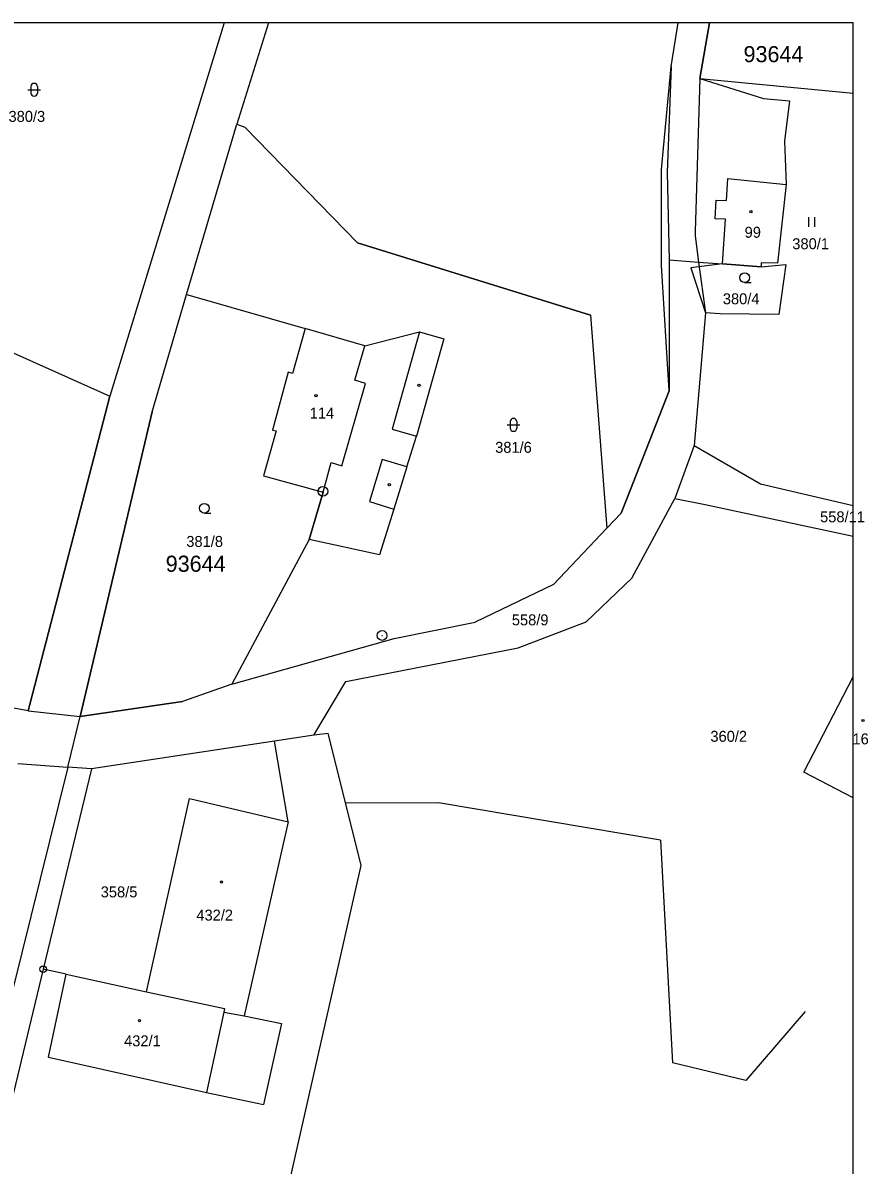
# Model space of a CAD drawing. Extents: x -778045 to -768365, y -1202571 to -1202059.
# Drawn here: x -777753.6 to -777622.5, y -1202457.4 to -1202280.1 of the extents above; entities that cross this region are included whole.
import ezdxf

# ---------------------------------------------------------------- set-up
doc = ezdxf.new("R2010")
doc.units = 0
for name, color, linetype in [('BPEJ', 7, 'Continuous'), ('Katastr_Hranice parcel', 7, 'Continuous'), ('Katastr_Parcelní čísla', 7, 'Continuous'), ('Katastr_Slučkované čáry', 7, 'Continuous'), ('Katastr_Značky kultur', 7, 'Continuous')]:
    doc.layers.add(name, color=color, linetype=linetype)

msp = doc.modelspace()

# ---------------------------------------------------------------- linework, layer by layer
at = {"layer": 'BPEJ'}
for points in [[(-777715.51, -1202280.12), (-777720.45, -1202295.86), (-777719.2, -1202296.33), (-777701.71, -1202314.27), (-777665.58, -1202325.46), (-777663.01, -1202358.54), (-777660.78, -1202356.18), (-777659.91, -1202353.96), (-777653.34, -1202337.23), (-777654.57, -1202317.8), (-777654.55, -1202302.89), (-777653.05, -1202286.88), (-777651.96, -1202280.12)], [(-777647.08, -1202280.12), (-777648.6, -1202288.78), (-777638.72, -1202291.84), (-777634.69, -1202292.2), (-777635.48, -1202298.47), (-777635.2, -1202305.22), (-777636.54, -1202317.41), (-777639.06, -1202317.35), (-777639.1, -1202318), (-777645.06, -1202317.53), (-777650.01, -1202318.12), (-777647.71, -1202325.12), (-777649.49, -1202345.7), (-777639.21, -1202351.67), (-777624.79, -1202354.99)], [(-777788.3, -1202316.49), (-777774.01, -1202322.88), (-777740.14, -1202338.03), (-777752.8, -1202386.89), (-777773.14, -1202383.15), (-777779.27, -1202388.61), (-777811.7, -1202375.6), (-777805.7, -1202356.3), (-777793.87, -1202330.63), (-777788.3, -1202316.49)], [(-777728.24, -1202322.3), (-777726.98, -1202322.66), (-777709.85, -1202327.57), (-777711.82, -1202334.53), (-777712.49, -1202334.34), (-777714.9, -1202343.3), (-777714.35, -1202343.45), (-777716.32, -1202350.41), (-777707.07, -1202352.95), (-777709.23, -1202360.29), (-777721.22, -1202382.72), (-777728.85, -1202385.43), (-777744.73, -1202387.77), (-777733.6, -1202340.49), (-777728.24, -1202322.3)]]:
    msp.add_lwpolyline(points, dxfattribs=at)
at = {"layer": 'Defpoints'}
for p, q in [((-777624.79, -1202280.12), (-778044.79, -1202280.12)), ((-777624.79, -1202569.12), (-777624.79, -1202280.12))]:
    msp.add_line(p, q, dxfattribs=at)
at = {"layer": 'Katastr_Hranice parcel'}
for p, q in [((-777648.6, -1202288.78), (-777624.79, -1202291.01)), ((-777714.61, -1202391.58), (-777743, -1202395.86)), ((-777708.49, -1202390.66), (-777714.61, -1202391.58)), ((-777712.49, -1202404.11), (-777714.61, -1202391.58)), ((-777743, -1202395.86), (-777750.49, -1202426.97)), ((-777750.49, -1202426.97), (-777772.39, -1202517.89)), ((-777746.91, -1202427.75), (-777750.49, -1202426.97))]:
    msp.add_line(p, q, dxfattribs=at)
for points in [[(-777722.39, -1202280.12), (-777740.14, -1202338.03)], [(-777715.51, -1202280.12), (-777720.45, -1202295.86)], [(-777653.05, -1202286.88), (-777651.96, -1202280.12)], [(-777648.6, -1202288.78), (-777647.08, -1202280.12)], [(-777653.05, -1202286.88), (-777653.66, -1202303.32)], [(-777648.6, -1202288.78), (-777649.33, -1202312.52)], [(-777648.6, -1202288.78), (-777638.72, -1202291.84)], [(-777638.72, -1202291.84), (-777634.69, -1202292.2)], [(-777634.69, -1202292.2), (-777635.48, -1202298.47)], [(-777728.24, -1202322.3), (-777720.45, -1202295.86)], [(-777720.45, -1202295.86), (-777719.2, -1202296.33)], [(-777701.71, -1202314.27), (-777719.2, -1202296.33)], [(-777635.48, -1202298.47), (-777635.2, -1202305.22)], [(-777653.66, -1202303.32), (-777653.34, -1202316.88)], [(-777635.2, -1202305.22), (-777636.54, -1202317.41)], [(-777649.33, -1202312.52), (-777649.34, -1202313.17), (-777648.79, -1202317.24)], [(-777665.58, -1202325.46), (-777701.71, -1202314.27)], [(-777653.34, -1202316.88), (-777653.34, -1202337.23)], [(-777653.34, -1202316.88), (-777648.79, -1202317.24)], [(-777648.79, -1202317.24), (-777645.06, -1202317.53)], [(-777648.79, -1202317.24), (-777647.71, -1202325.12)], [(-777645.06, -1202317.53), (-777639.1, -1202318)], [(-777639.06, -1202317.35), (-777639.1, -1202318)], [(-777639.1, -1202318), (-777635.26, -1202317.6)], [(-777636.54, -1202317.41), (-777639.06, -1202317.35)], [(-777635.26, -1202317.6), (-777636.36, -1202325.39)], [(-777774.01, -1202322.88), (-777740.14, -1202338.03)], [(-777733.6, -1202340.49), (-777728.24, -1202322.3)], [(-777728.24, -1202322.3), (-777726.98, -1202322.66)], [(-777726.98, -1202322.66), (-777709.85, -1202327.57)], [(-777665.58, -1202325.46), (-777663.01, -1202358.54)], [(-777647.71, -1202325.12), (-777649.49, -1202345.7)], [(-777645.43, -1202325.29), (-777647.71, -1202325.12)], [(-777636.36, -1202325.39), (-777645.43, -1202325.29)], [(-777709.85, -1202327.57), (-777711.82, -1202334.53)], [(-777700.6, -1202330.22), (-777709.85, -1202327.57)], [(-777700.6, -1202330.22), (-777692.1, -1202328.08)], [(-777692.1, -1202328.08), (-777688.3, -1202329.15)], [(-777688.3, -1202329.15), (-777692.54, -1202344.26)], [(-777712.49, -1202334.34), (-777714.9, -1202343.3)], [(-777711.82, -1202334.53), (-777712.49, -1202334.34)], [(-777653.34, -1202337.23), (-777659.91, -1202353.96)], [(-777752.8, -1202386.89), (-777740.14, -1202338.03)], [(-777733.6, -1202340.49), (-777744.73, -1202387.77)], [(-777714.35, -1202343.45), (-777716.32, -1202350.41)], [(-777714.9, -1202343.3), (-777714.35, -1202343.45)], [(-777694.06, -1202349.02), (-777692.54, -1202344.26)], [(-777649.49, -1202345.7), (-777652.48, -1202353.91)], [(-777649.49, -1202345.7), (-777639.21, -1202351.67)], [(-777694.06, -1202349.02), (-777696.1, -1202355.56)], [(-777716.32, -1202350.41), (-777707.07, -1202352.95)], [(-777709.23, -1202360.29), (-777707.07, -1202352.95)], [(-777639.21, -1202351.67), (-777624.79, -1202354.99)], [(-777659.91, -1202353.96), (-777660.78, -1202356.18)], [(-777659.17, -1202366.28), (-777652.48, -1202353.91)], [(-777652.48, -1202353.91), (-777647.75, -1202354.88)], [(-777647.75, -1202354.88), (-777624.79, -1202359.75)], [(-777696.1, -1202355.56), (-777698.31, -1202362.67)], [(-777660.78, -1202356.18), (-777663.01, -1202358.54)], [(-777663.01, -1202358.54), (-777671.31, -1202367.29)], [(-777709.23, -1202360.29), (-777721.22, -1202382.72)], [(-777698.31, -1202362.67), (-777709.23, -1202360.29)], [(-777671.31, -1202367.29), (-777683.45, -1202373.1)], [(-777666.24, -1202373.06), (-777659.17, -1202366.28)], [(-777696.04, -1202375.65), (-777683.45, -1202373.1)], [(-777676.8, -1202377.11), (-777666.24, -1202373.06)], [(-777721.22, -1202382.72), (-777696.04, -1202375.65)], [(-777703.53, -1202382.3), (-777676.8, -1202377.11)], [(-777632.44, -1202396.39), (-777624.79, -1202381.58)], [(-777752.8, -1202386.89), (-777773.14, -1202383.15)], [(-777721.22, -1202382.72), (-777728.85, -1202385.43)], [(-777708.49, -1202390.66), (-777703.53, -1202382.3)], [(-777752.8, -1202386.89), (-777744.73, -1202387.77)], [(-777744.73, -1202387.77), (-777728.85, -1202385.43)], [(-777746.67, -1202395.6), (-777744.73, -1202387.77)], [(-777706.27, -1202390.41), (-777708.49, -1202390.66)], [(-777703.6, -1202401.08), (-777706.27, -1202390.41)], [(-777746.67, -1202395.6), (-777776.75, -1202516.88)], [(-777754.4, -1202395.04), (-777746.67, -1202395.6)], [(-777743, -1202395.86), (-777746.67, -1202395.6)], [(-777624.79, -1202400.38), (-777632.44, -1202396.39)], [(-777734.48, -1202430.48), (-777727.79, -1202400.47)], [(-777727.79, -1202400.47), (-777712.49, -1202404.11)], [(-777701.15, -1202410.88), (-777703.6, -1202401.08)], [(-777703.6, -1202401.08), (-777689.17, -1202401.13)], [(-777654.68, -1202406.95), (-777689.17, -1202401.13)], [(-777712.49, -1202404.11), (-777719.28, -1202434.19)], [(-777654.68, -1202406.95), (-777652.82, -1202441.51)], [(-777727.56, -1202527.62), (-777701.15, -1202410.88)], [(-777749.69, -1202440.6), (-777746.91, -1202427.75)], [(-777746.91, -1202427.75), (-777734.48, -1202430.48)], [(-777734.48, -1202430.48), (-777722.37, -1202433.08)], [(-777722.37, -1202433.08), (-777722.48, -1202433.61)], [(-777722.48, -1202433.61), (-777719.28, -1202434.19)], [(-777719.28, -1202434.19), (-777713.51, -1202435.38)], [(-777632.26, -1202433.53), (-777641.45, -1202444.21)], [(-777713.51, -1202435.38), (-777716.29, -1202447.95)], [(-777749.69, -1202440.6), (-777725.13, -1202446.07)], [(-777641.45, -1202444.21), (-777652.82, -1202441.51)], [(-777725.13, -1202446.07), (-777716.29, -1202447.95)]]:
    msp.add_lwpolyline(points, dxfattribs=at)
at = {"layer": 'Katastr_Slučkované čáry'}
for points in [[(-777644.45, -1202307.69), (-777644.24, -1202304.29)], [(-777644.24, -1202304.29), (-777635.2, -1202305.22)], [(-777646.22, -1202310.52), (-777646.07, -1202307.64)], [(-777646.07, -1202307.64), (-777644.45, -1202307.69)], [(-777644.63, -1202310.61), (-777646.22, -1202310.52)], [(-777645.06, -1202317.53), (-777644.63, -1202310.61)], [(-777692.1, -1202328.08), (-777696.34, -1202343.19)], [(-777702.13, -1202335.55), (-777700.6, -1202330.22)], [(-777700.46, -1202336.06), (-777702.13, -1202335.55)], [(-777704.14, -1202348.88), (-777700.46, -1202336.06)], [(-777696.34, -1202343.19), (-777692.54, -1202344.26)], [(-777697.89, -1202347.88), (-777699.83, -1202354.38)], [(-777694.06, -1202349.02), (-777697.89, -1202347.88)], [(-777707.07, -1202352.95), (-777705.8, -1202348.34)], [(-777705.8, -1202348.34), (-777704.14, -1202348.88)], [(-777699.83, -1202354.38), (-777696.1, -1202355.56)], [(-777722.48, -1202433.61), (-777725.13, -1202446.07)]]:
    msp.add_lwpolyline(points, dxfattribs=at)
at = {"layer": 'Katastr_Značky kultur'}
for p, q in [((-777752.89, -1202290.51), (-777750.89, -1202290.51)), ((-777752.39, -1202290.01), (-777752.39, -1202291.01)), ((-777751.39, -1202290.01), (-777751.39, -1202291.01)), ((-777631.73, -1202310.25), (-777631.73, -1202311.75)), ((-777630.73, -1202311.75), (-777630.73, -1202310.25)), ((-777641.65, -1202320.41), (-777640.65, -1202320.41)), ((-777678.51, -1202342.5), (-777676.51, -1202342.5)), ((-777678.01, -1202342), (-777678.01, -1202343)), ((-777677.01, -1202342), (-777677.01, -1202343)), ((-777707.14, -1202352.82), (-777707.04, -1202352.82)), ((-777725.48, -1202356.19), (-777724.48, -1202356.19)), ((-777697.95, -1202375.18), (-777697.85, -1202375.18)), ((-777750.54, -1202426.97), (-777750.44, -1202426.97))]:
    msp.add_line(p, q, dxfattribs=at)
for centre, radius in [((-777640.68, -1202309.44), 0.175), ((-777641.65, -1202319.66), 0.75), ((-777692.19, -1202336.36), 0.175), ((-777708.15, -1202337.98), 0.175), ((-777707.09, -1202352.82), 0.756), ((-777696.79, -1202351.8), 0.175), ((-777725.48, -1202355.44), 0.75), ((-777697.9, -1202375.18), 0.756), ((-777623.28, -1202388.38), 0.175), ((-777722.82, -1202413.45), 0.175), ((-777750.49, -1202426.97), 0.499), ((-777735.54, -1202434.94), 0.175)]:
    msp.add_circle(centre, radius, dxfattribs=at)
for centre, start, end in [((-777751.89, -1202290.01), 0, 180), ((-777751.89, -1202291.01), 180, 0), ((-777677.51, -1202342), 0, 180), ((-777677.51, -1202343), 180, 0)]:
    msp.add_arc(centre, 0.5, start, end, dxfattribs=at)

# ---------------------------------------------------------------- texts
at = {"layer": 'BPEJ'}
for p in [(-777641.82, -1202286.23), (-777731.48, -1202365.3)]:
    msp.add_text('93644', height=2.5, dxfattribs=at).set_placement(p)
at = {"layer": 'Katastr_Parcelní čísla'}
for s, p in [('380/3', (-777755.87, -1202295.49)), ('99', (-777641.65, -1202313.47)), ('380/1', (-777634.25, -1202315.25)), ('380/4', (-777645.03, -1202323.79)), ('114', (-777709.13, -1202341.52)), ('381/6', (-777680.36, -1202346.84)), ('558/11', (-777629.94, -1202357.62)), ('381/8', (-777728.28, -1202361.44)), ('558/9', (-777677.77, -1202373.61)), ('360/2', (-777646.96, -1202391.68)), ('16', (-777624.91, -1202392.08)), ('358/5', (-777741.56, -1202415.82)), ('432/2', (-777726.72, -1202419.42)), ('432/1', (-777737.93, -1202438.93))]:
    msp.add_text(s, height=1.7, dxfattribs=at).set_placement(p)

doc.saveas('drawing.dxf')
